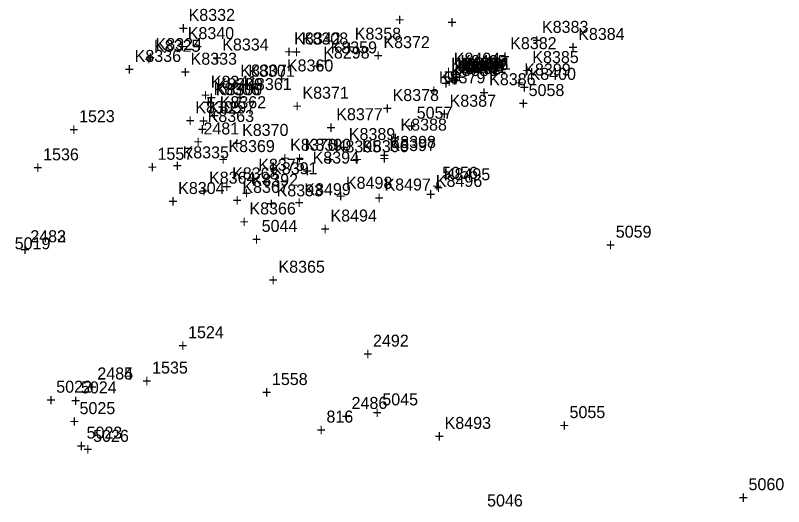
# Model space of a CAD drawing. Extents: x 1036751 to 1042192, y 772604 to 785439.
# Drawn here: x 1038800.7 to 1038960.7, y 778008.5 to 778110.9 of the extents above; entities that cross this region are included whole.
import ezdxf

# ---------------------------------------------------------------- set-up
doc = ezdxf.new("R2010")
doc.units = 0
for name, color, linetype in [('S_Control_Temp_Traverse', 7, 'Continuous'), ('S_Curb_Type_3', 7, 'Continuous'), ('S_Drainage_Culvert_Top', 7, 'Continuous'), ('S_Drainage_Invert', 7, 'Continuous'), ('S_Fencing_StockadePostPlank', 7, 'Continuous'), ('S_Ground_Elevation', 7, 'Continuous'), ('S_Ground_LevelString', 7, 'Continuous'), ('S_Property_IronPipeFound', 7, 'Continuous'), ('S_Property_Mailbox', 7, 'Continuous'), ('S_Roadway_Centerline', 7, 'Continuous'), ('S_Roadway_Drive_Paved', 7, 'Continuous'), ('S_Roadway_Edge_Pavement', 7, 'Continuous'), ('S_Roadway_Painted_Lines', 7, 'Continuous'), ('S_Traffic_Sign_SinglePost', 7, 'Continuous'), ('S_Trees_TreeLine', 7, 'Continuous'), ('S_Utilities_Pole_Brace3', 7, 'Continuous'), ('S_Utilities_Pole_Power', 7, 'Continuous')]:
    doc.layers.add(name, color=color, linetype=linetype)

msp = doc.modelspace()

# ---------------------------------------------------------------- texts
at = {"layer": 'S_Control_Temp_Traverse'}
for s, p in [('816', (1038865.5, 778025.99)), ('816', (1038865.5, 778025.99)), ('816', (1038865.5, 778025.99)), ('+', (1038863.44, 778023.24)), ('+', (1038863.44, 778023.24)), ('+', (1038863.44, 778023.24))]:
    msp.add_text(s, height=2.5, dxfattribs=at).set_placement(p)
at = {"layer": 'S_Curb_Type_3'}
for s, p in [('K8301', (1038849.23, 778098.05)), ('K8300', (1038842.45, 778094.19)), ('+', (1038847.17, 778095.3)), ('+', (1038840.39, 778091.44))]:
    msp.add_text(s, height=2.5, dxfattribs=at).set_placement(p)
at = {"layer": 'S_Drainage_Culvert_Top'}
for s, p in [('K8408', (1038892.69, 778099.28)), ('+', (1038890.63, 778096.53)), ('2483', (1038803.82, 778063.57)), ('+', (1038801.76, 778060.82)), ('2484', (1038817.79, 778034.96)), ('+', (1038815.73, 778032.21))]:
    msp.add_text(s, height=2.5, dxfattribs=at).set_placement(p)
at = {"layer": 'S_Drainage_Invert'}
for s, p in [('K8409', (1038892.97, 778098.92)), ('+', (1038890.9, 778096.17)), ('2482', (1038803.83, 778063.57)), ('+', (1038801.77, 778060.82)), ('2485', (1038817.79, 778034.97)), ('+', (1038815.73, 778032.22))]:
    msp.add_text(s, height=2.5, dxfattribs=at).set_placement(p)
at = {"layer": 'S_Fencing_StockadePostPlank'}
for s, p in [('K8399', (1038906.7, 778098.33)), ('+', (1038904.64, 778095.58)), ('K8398', (1038878.64, 778083.23)), ('+', (1038876.58, 778080.48))]:
    msp.add_text(s, height=2.5, dxfattribs=at).set_placement(p)
at = {"layer": 'S_Ground_Elevation'}
for s, p in [('+', (1038879.79, 778108.72)), ('+', (1038890.68, 778108.19)), ('K8383', (1038910.39, 778107.21)), ('K8358', (1038871.39, 778105.79)), ('K8384', (1038917.93, 778105.73)), ('K8372', (1038877.37, 778104.02)), ('K8382', (1038903.77, 778103.81)), ('+', (1038908.33, 778104.46)), ('K8359', (1038866.36, 778102.93)), ('+', (1038869.33, 778103.04)), ('+', (1038915.87, 778102.98)), ('+', (1038875.31, 778101.27)), ('K8404', (1038892.01, 778100.58)), ('K8405', (1038893.4, 778100.08)), ('+', (1038901.71, 778101.06)), ('K8385', (1038908.38, 778100.91)), ('K8360', (1038857.26, 778099.17)), ('+', (1038864.3, 778100.18)), ('K8403', (1038891.45, 778099.53)), ('K8402', (1038892.14, 778098.59)), ('K8401', (1038893.29, 778098.83)), ('K8407', (1038893.56, 778098.88)), ('K8406', (1038893.73, 778099.44)), ('K8381', (1038894.26, 778099.56)), ('K8379', (1038888.94, 778096.69)), ('+', (1038889.95, 778097.83)), ('+', (1038891.34, 778097.33)), ('K8380', (1038891.48, 778098.21)), ('+', (1038906.32, 778098.16)), ('K8400', (1038907.8, 778097.41)), ('K8361', (1038848.59, 778095.29)), ('+', (1038855.2, 778096.42)), ('+', (1038889.39, 778096.78)), ('+', (1038890.08, 778095.84)), ('+', (1038891.23, 778096.08)), ('+', (1038891.5, 778096.13)), ('+', (1038891.67, 778096.69)), ('+', (1038892.19, 778096.81)), ('K8386', (1038899.39, 778096.3)), ('K8371', (1038860.5, 778093.48)), ('+', (1038886.88, 778093.94)), ('+', (1038889.42, 778095.46)), ('+', (1038905.74, 778094.66)), ('5058', (1038907.61, 778094.04)), ('+', (1038846.53, 778092.54)), ('K8378', (1038879.27, 778093)), ('+', (1038897.33, 778093.55)), ('K8362', (1038843.27, 778091.51)), ('+', (1038858.44, 778090.73)), ('K8387', (1038891.15, 778091.81)), ('+', (1038905.54, 778091.29)), ('K8377', (1038867.54, 778089.01)), ('+', (1038877.21, 778090.25)), ('5057', (1038884.3, 778089.32)), ('K8363', (1038840.76, 778088.63)), ('+', (1038841.21, 778088.76)), ('+', (1038889.09, 778089.07)), ('K8370', (1038847.93, 778085.73)), ('+', (1038865.48, 778086.26)), ('K8388', (1038880.92, 778086.83)), ('+', (1038882.24, 778086.57)), ('+', (1038838.69, 778085.88)), ('K8389', (1038870.16, 778084.87)), ('K8369', (1038845.08, 778082.36)), ('+', (1038845.87, 778082.98)), ('K8376', (1038857.93, 778082.64)), ('K8390', (1038860.99, 778082.64)), ('K8395', (1038867.23, 778082.3)), ('K8396', (1038872.94, 778082.35)), ('K8397', (1038878.63, 778082.57)), ('+', (1038878.86, 778084.08)), ('+', (1038868.09, 778082.12)), ('+', (1038843.02, 778079.61)), ('+', (1038855.86, 778079.89)), ('+', (1038858.93, 778079.89)), ('K8394', (1038862.62, 778079.97)), ('+', (1038865.17, 778079.55)), ('+', (1038870.88, 778079.6)), ('+', (1038876.57, 778079.82)), ('K8375', (1038851.3, 778078.47)), ('K8391', (1038853.98, 778077.73)), ('K8368', (1038845.85, 778076.68)), ('+', (1038860.56, 778077.22)), ('5056', (1038889.61, 778076.8)), ('K8364', (1038841.05, 778075.78)), ('+', (1038849.23, 778075.72)), ('K8392', (1038849.92, 778075.33)), ('+', (1038851.92, 778074.98)), ('K8498', (1038869.56, 778074.71)), ('K8497', (1038877.58, 778074.35)), ('K8496', (1038888.28, 778075.11)), ('+', (1038843.79, 778073.93)), ('K8367', (1038847.99, 778073.85)), ('K8393', (1038855.12, 778073.13)), ('K8499', (1038860.9, 778073.37)), ('+', (1038887.55, 778074.05)), ('+', (1038838.99, 778073.03)), ('+', (1038847.86, 778072.58)), ('+', (1038867.5, 778071.96)), ('+', (1038875.52, 778071.6)), ('+', (1038886.22, 778072.36)), ('+', (1038845.92, 778071.1)), ('+', (1038853.05, 778070.38)), ('+', (1038858.84, 778070.62)), ('K8366', (1038849.46, 778069.36)), ('+', (1038847.4, 778066.61)), ('5044', (1038852.01, 778065.73)), ('5059', (1038925.76, 778064.52)), ('5019', (1038800.58, 778062.1)), ('+', (1038849.95, 778062.98)), ('+', (1038923.7, 778061.77)), ('K8365', (1038855.51, 778057.22)), ('+', (1038853.45, 778054.47)), ('5022', (1038809.23, 778032.21)), ('5024', (1038814.37, 778032.07)), ('5045', (1038877.14, 778029.57)), ('+', (1038807.17, 778029.46)), ('+', (1038812.31, 778029.32)), ('5025', (1038814.08, 778027.75)), ('+', (1038875.08, 778026.82)), ('5055', (1038916.13, 778026.92)), ('+', (1038812.02, 778025)), ('+', (1038914.07, 778024.17)), ('5023', (1038815.55, 778022.64)), ('5026', (1038816.91, 778021.97)), ('+', (1038813.49, 778019.89)), ('+', (1038814.85, 778019.22)), ('5060', (1038953.41, 778011.88)), ('+', (1038951.35, 778009.13)), ('5046', (1038898.96, 778008.5))]:
    msp.add_text(s, height=2.5, dxfattribs=at).set_placement(p)
at = {"layer": 'S_Ground_LevelString'}
for s, p in [('K8340', (1038836.61, 778105.9)), ('K8342', (1038858.78, 778104.8)), ('+', (1038834.55, 778103.15)), ('+', (1038856.72, 778102.05)), ('K8336', (1038825.56, 778101.15)), ('+', (1038823.49, 778098.4)), ('K8341', (1038841.41, 778095.76)), ('+', (1038839.35, 778093.01)), ('K8335', (1038835.53, 778081.05)), ('+', (1038833.47, 778078.3))]:
    msp.add_text(s, height=2.5, dxfattribs=at).set_placement(p)
at = {"layer": 'S_Property_IronPipeFound'}
for s, p in [('2492', (1038875.2, 778041.81)), ('+', (1038873.13, 778039.06))]:
    msp.add_text(s, height=2.5, dxfattribs=at).set_placement(p)
at = {"layer": 'S_Property_Mailbox'}
for s, p in [('K8299', (1038842.61, 778095.26)), ('+', (1038840.55, 778092.51))]:
    msp.add_text(s, height=2.5, dxfattribs=at).set_placement(p)
at = {"layer": 'S_Roadway_Centerline'}
for s, p in [('1523', (1038813.98, 778088.59)), ('+', (1038811.92, 778085.84)), ('1524', (1038836.69, 778043.57)), ('+', (1038834.63, 778040.82))]:
    msp.add_text(s, height=2.5, dxfattribs=at).set_placement(p)
at = {"layer": 'S_Roadway_Drive_Paved'}
for s, p in [('K8308', (1038860.37, 778104.78)), ('+', (1038858.31, 778102.03)), ('K8307', (1038847.57, 778098.11)), ('K8306', (1038842, 778094.25)), ('+', (1038845.51, 778095.36)), ('K8305', (1038838.2, 778090.47)), ('+', (1038839.94, 778091.5)), ('+', (1038836.14, 778087.72)), ('K8304', (1038834.62, 778073.62)), ('+', (1038832.56, 778070.87))]:
    msp.add_text(s, height=2.5, dxfattribs=at).set_placement(p)
at = {"layer": 'S_Roadway_Edge_Pavement'}
for s, p in [('1557', (1038830.32, 778080.75)), ('1536', (1038806.5, 778080.64)), ('+', (1038828.26, 778078)), ('+', (1038804.44, 778077.89)), ('1535', (1038829.2, 778036.2)), ('+', (1038827.14, 778033.45)), ('1558', (1038854.15, 778033.81)), ('+', (1038852.08, 778031.06))]:
    msp.add_text(s, height=2.5, dxfattribs=at).set_placement(p)
at = {"layer": 'S_Roadway_Painted_Lines'}
for s, p in [('K8332', (1038836.79, 778109.7)), ('+', (1038834.73, 778106.95)), ('K8325', (1038829.59, 778103.26)), ('K8324', (1038829.91, 778103.62)), ('K8334', (1038843.8, 778103.53)), ('+', (1038827.53, 778100.51)), ('+', (1038827.85, 778100.87)), ('K8333', (1038837.21, 778100.57)), ('+', (1038841.74, 778100.78)), ('+', (1038835.15, 778097.82))]:
    msp.add_text(s, height=2.5, dxfattribs=at).set_placement(p)
at = {"layer": 'S_Traffic_Sign_SinglePost'}
for s, p in [('2486', (1038870.74, 778028.83)), ('+', (1038868.68, 778026.08))]:
    msp.add_text(s, height=2.5, dxfattribs=at).set_placement(p)
at = {"layer": 'S_Trees_TreeLine'}
for s, p in [('K8495', (1038889.94, 778076.49)), ('+', (1038887.88, 778073.74)), ('K8494', (1038866.34, 778067.88)), ('+', (1038864.28, 778065.13)), ('K8493', (1038890.11, 778024.66)), ('+', (1038888.05, 778021.91))]:
    msp.add_text(s, height=2.5, dxfattribs=at).set_placement(p)
at = {"layer": 'S_Utilities_Pole_Brace3'}
for s, p in [('K8298', (1038864.83, 778101.85)), ('+', (1038862.77, 778099.1))]:
    msp.add_text(s, height=2.5, dxfattribs=at).set_placement(p)
at = {"layer": 'S_Utilities_Pole_Power'}
for s, p in [('K8297', (1038841, 778090.4)), ('+', (1038838.94, 778087.65)), ('2481', (1038839.89, 778086.03)), ('+', (1038837.83, 778083.28))]:
    msp.add_text(s, height=2.5, dxfattribs=at).set_placement(p)

doc.saveas('drawing.dxf')
